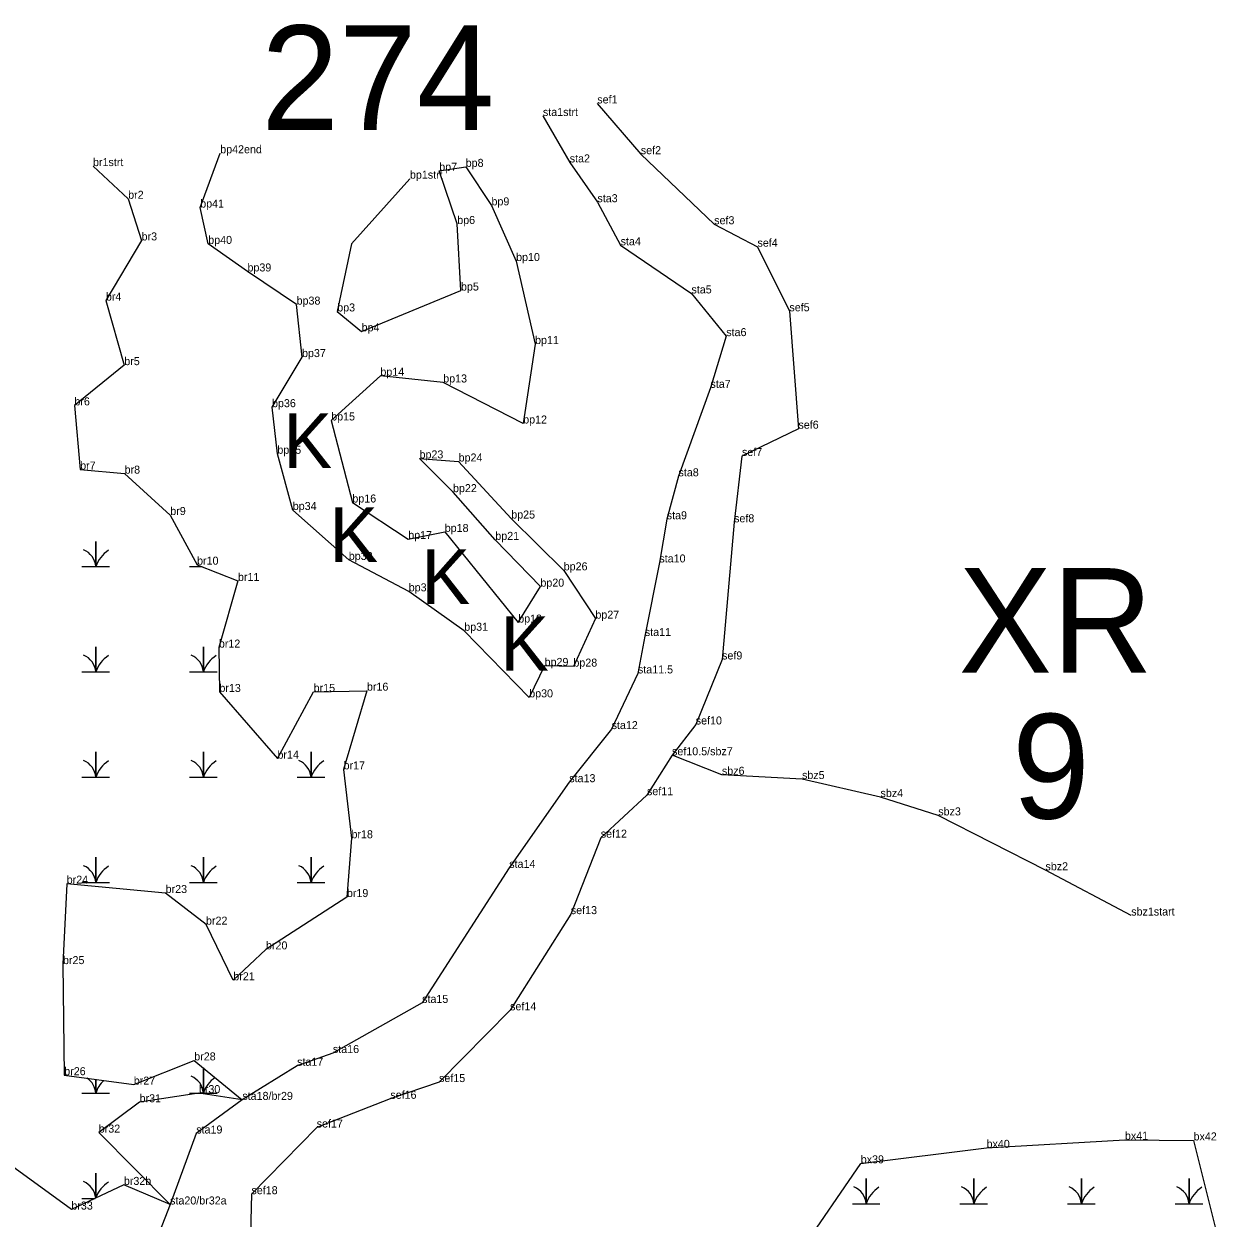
# Model space of a CAD drawing. Extents: x 2072529 to 2268796, y 436423 to 470406.
# Drawn here: x 2233128 to 2233875, y 438303 to 439049 of the extents above; entities that cross this region are included whole.
import ezdxf

# ---------------------------------------------------------------- set-up
doc = ezdxf.new("R2010")
doc.units = 0
for name, color, linetype in [('Default', 7, 'Continuous'), ('Exist Environmental Wetland Boundary Cogo Comment', 7, 'Continuous'), ('Exist Environmental Wetland Boundary Cogo Point CELL', 7, 'Continuous'), ('Exist Hydro Jurisdictional Stream or Body of Water NEU Mitigable Cogo Comment', 7, 'Continuous'), ('Old_Level_20', 7, 'Continuous'), ('Old_Level_52', 7, 'Continuous')]:
    doc.layers.add(name, color=color, linetype=linetype)

msp = doc.modelspace()

# ---------------------------------------------------------------- linework, layer by layer
at = {"layer": 'Exist Environmental Wetland Boundary Cogo Point CELL'}
for points in [[(2233164.16, 438710.03), (2233172.76, 438710.03), (2233172.76, 438725.81), (2233172.76, 438710.03), (2233181.36, 438710.03)], [(2233231.41, 438710.03), (2233239.16, 438710.03)], [(2233164.16, 438644.23), (2233172.76, 438644.23), (2233172.76, 438660.01), (2233172.76, 438644.23), (2233181.36, 438644.23)], [(2233231.41, 438644.23), (2233240.01, 438644.23), (2233240.01, 438660.01), (2233240.01, 438644.23), (2233248.61, 438644.23)], [(2233164.16, 438578.43), (2233172.76, 438578.43), (2233172.76, 438594.21), (2233172.76, 438578.43), (2233181.36, 438578.43)], [(2233231.41, 438578.43), (2233240.01, 438578.43), (2233240.01, 438594.21), (2233240.01, 438578.43), (2233248.61, 438578.43)], [(2233298.66, 438578.43), (2233307.26, 438578.43), (2233307.26, 438594.21), (2233307.26, 438578.43), (2233315.86, 438578.43)], [(2233164.16, 438512.63), (2233172.76, 438512.63), (2233172.76, 438528.41), (2233172.76, 438512.63), (2233181.36, 438512.63)], [(2233231.41, 438512.63), (2233240.01, 438512.63), (2233240.01, 438528.41), (2233240.01, 438512.63), (2233248.61, 438512.63)], [(2233298.66, 438512.63), (2233307.26, 438512.63), (2233307.26, 438528.41), (2233307.26, 438512.63), (2233315.86, 438512.63)], [(2233231.41, 438381.03), (2233240.01, 438381.03), (2233240.01, 438396.78)], [(2233240.01, 438396.78), (2233240.01, 438381.03), (2233248.61, 438381.03)], [(2233164.16, 438381.03), (2233172.76, 438381.03), (2233172.76, 438389.55)], [(2233172.76, 438389.55), (2233172.76, 438381.03), (2233181.36, 438381.03)], [(2233172.76, 438315.4), (2233172.76, 438331.01), (2233172.76, 438315.4)], [(2233645.48, 438311.93), (2233654.08, 438311.93), (2233654.08, 438327.71), (2233654.08, 438311.93), (2233662.68, 438311.93)], [(2233712.73, 438311.93), (2233721.33, 438311.93), (2233721.33, 438327.71), (2233721.33, 438311.93), (2233729.93, 438311.93)], [(2233779.98, 438311.93), (2233788.58, 438311.93), (2233788.58, 438327.71), (2233788.58, 438311.93), (2233797.18, 438311.93)], [(2233847.23, 438311.93), (2233855.83, 438311.93), (2233855.83, 438327.71), (2233855.83, 438311.93), (2233864.43, 438311.93)], [(2233164.16, 438315.23), (2233172.4, 438315.23)]]:
    msp.add_lwpolyline(points, dxfattribs=at)
for centre, radius, start, end in [((2233160.49, 438709.15), 12.3, 4.14034, 67.53497), ((2233191, 438703.97), 19.22, 122.12745, 161.62219), ((2233160.49, 438643.35), 12.3, 4.14034, 67.53497), ((2233191, 438638.17), 19.22, 122.12745, 161.62219), ((2233227.74, 438643.35), 12.3, 4.14034, 67.53497), ((2233258.25, 438638.17), 19.22, 122.12745, 161.62219), ((2233160.49, 438577.55), 12.3, 4.14034, 67.53497), ((2233191, 438572.37), 19.22, 122.12745, 161.62219), ((2233227.74, 438577.55), 12.3, 4.14034, 67.53497), ((2233258.25, 438572.37), 19.22, 122.12745, 161.62219), ((2233294.99, 438577.55), 12.3, 4.14034, 67.53497), ((2233325.5, 438572.37), 19.22, 122.12745, 161.62219), ((2233160.49, 438511.75), 12.3, 4.14034, 67.53497), ((2233191, 438506.57), 19.22, 122.12745, 161.62219), ((2233227.74, 438511.75), 12.3, 4.14034, 67.53497), ((2233258.25, 438506.57), 19.22, 122.12745, 161.62219), ((2233294.99, 438511.75), 12.3, 4.14034, 67.53497), ((2233325.5, 438506.57), 19.22, 122.12745, 161.62219), ((2233227.74, 438380.15), 12.3, 4.14034, 67.53497), ((2233258.25, 438374.97), 19.22, 124.68213, 161.62219), ((2233160.49, 438380.15), 12.3, 4.14034, 55.31148), ((2233191, 438374.97), 19.22, 133.6793, 161.62219), ((2233160.49, 438314.35), 12.3, 4.88803, 67.53497), ((2233191, 438309.17), 19.22, 122.12745, 161.0015), ((2233641.81, 438311.04), 12.3, 4.14034, 67.53497), ((2233672.32, 438305.87), 19.22, 122.12745, 161.62219), ((2233709.06, 438311.04), 12.3, 4.14034, 67.53497), ((2233739.57, 438305.87), 19.22, 122.12745, 161.62219), ((2233776.31, 438311.04), 12.3, 4.14034, 67.53497), ((2233806.82, 438305.87), 19.22, 122.12745, 161.62219), ((2233843.56, 438311.04), 12.3, 4.14034, 67.53497), ((2233874.07, 438305.87), 19.22, 122.12745, 161.62219)]:
    msp.add_arc(centre, radius, start, end, dxfattribs=at)
at = {"layer": 'Old_Level_20'}
for p, q in [((2233486.12, 438999.5), (2233486.12, 438999.5)), ((2233452.15, 438991.66), (2233452.15, 438991.66)), ((2233250.54, 438968.37), (2233250.54, 438968.37)), ((2233513.33, 438967.79), (2233513.33, 438967.79)), ((2233171.06, 438960.35), (2233171.06, 438960.35)), ((2233403.91, 438959.87), (2233403.91, 438959.87)), ((2233468.9, 438962.65), (2233468.9, 438962.65)), ((2233387.35, 438957.42), (2233387.35, 438957.42)), ((2233193.01, 438939.93), (2233193.01, 438939.93)), ((2233420.01, 438935.81), (2233420.01, 438935.81)), ((2233486.21, 438937.78), (2233486.21, 438937.78)), ((2233238.03, 438934.45), (2233238.03, 438934.45)), ((2233398.61, 438924.17), (2233398.61, 438924.17)), ((2233559.17, 438924.01), (2233559.17, 438924.01)), ((2233201.42, 438913.9), (2233201.42, 438913.9)), ((2233243.05, 438911.72), (2233243.05, 438911.72)), ((2233500.71, 438910.85), (2233500.71, 438910.85)), ((2233586.22, 438909.97), (2233586.22, 438909.97)), ((2233435.4, 438901.03), (2233435.4, 438901.03)), ((2233267.57, 438894.51), (2233267.57, 438894.51)), ((2233179.1, 438876.33), (2233179.1, 438876.33)), ((2233400.97, 438882.57), (2233400.97, 438882.57)), ((2233544.96, 438880.77), (2233544.96, 438880.77)), ((2233298.26, 438873.8), (2233298.26, 438873.8)), ((2233323.62, 438869.52), (2233323.62, 438869.52)), ((2233606.16, 438869.63), (2233606.16, 438869.63)), ((2233338.88, 438857.06), (2233338.88, 438857.06)), ((2233566.69, 438854.09), (2233566.69, 438854.09)), ((2233447.25, 438849.14), (2233447.25, 438849.14)), ((2233301.66, 438841), (2233301.66, 438841)), ((2233190.6, 438835.95), (2233190.6, 438835.95)), ((2233350.61, 438829.32), (2233350.61, 438829.32)), ((2233389.86, 438825.12), (2233389.86, 438825.12)), ((2233556.83, 438821.76), (2233556.83, 438821.76)), ((2233159.43, 438810.81), (2233159.43, 438810.81)), ((2233282.91, 438809.69), (2233282.91, 438809.69)), ((2233319.87, 438801.39), (2233319.87, 438801.39)), ((2233439.82, 438799.48), (2233439.82, 438799.48)), ((2233611.8, 438796.23), (2233611.8, 438796.23)), ((2233286.24, 438780.56), (2233286.24, 438780.56)), ((2233576.52, 438779.17), (2233576.52, 438779.17)), ((2233375.06, 438777.67), (2233375.06, 438777.67)), ((2233399.5, 438775.74), (2233399.5, 438775.74)), ((2233163.02, 438770.7), (2233163.02, 438770.7)), ((2233190.8, 438768.17), (2233190.8, 438768.17)), ((2233536.87, 438766.48), (2233536.87, 438766.48)), ((2233395.99, 438756.59), (2233395.99, 438756.59)), ((2233333.11, 438750.11), (2233333.11, 438750.11)), ((2233219.34, 438742.29), (2233219.34, 438742.29)), ((2233295.86, 438745.43), (2233295.86, 438745.43)), ((2233432.37, 438740.1), (2233432.37, 438740.1)), ((2233529.52, 438739.65), (2233529.52, 438739.65)), ((2233571.58, 438737.75), (2233571.58, 438737.75)), ((2233368, 438727.3), (2233368, 438727.3)), ((2233390.81, 438731.69), (2233390.81, 438731.69)), ((2233422.42, 438726.76), (2233422.42, 438726.76)), ((2233330.86, 438714.21), (2233330.86, 438714.21)), ((2233524.92, 438712.66), (2233524.92, 438712.66)), ((2233236.09, 438711.26), (2233236.09, 438711.26)), ((2233465.14, 438707.71), (2233465.14, 438707.71)), ((2233261.63, 438701.08), (2233261.63, 438701.08)), ((2233450.58, 438697.52), (2233450.58, 438697.52)), ((2233368.31, 438694.6), (2233368.31, 438694.6)), ((2233436.71, 438675.09), (2233436.71, 438675.09)), ((2233484.94, 438677.54), (2233484.94, 438677.54)), ((2233403.01, 438669.96), (2233403.01, 438669.96)), ((2233249.69, 438659.45), (2233249.69, 438659.45)), ((2233515.84, 438666.68), (2233515.84, 438666.68)), ((2233564.1, 438652.03), (2233564.1, 438652.03)), ((2233453.22, 438647.98), (2233453.22, 438647.98)), ((2233471.2, 438647.57), (2233471.2, 438647.57)), ((2233511.52, 438643.3), (2233511.52, 438643.3)), ((2233250.03, 438631.71), (2233250.03, 438631.71)), ((2233308.92, 438631.76), (2233308.92, 438631.76)), ((2233342.21, 438632.51), (2233342.21, 438632.51)), ((2233443.58, 438628.34), (2233443.58, 438628.34)), ((2233495.08, 438608.51), (2233495.08, 438608.51)), ((2233547.64, 438611.4), (2233547.64, 438611.4)), ((2233286.3, 438590.05), (2233286.3, 438590.05)), ((2233532.82, 438592.15), (2233532.82, 438592.15)), ((2233327.62, 438583.34), (2233327.62, 438583.34)), ((2233564, 438579.97), (2233564, 438579.97)), ((2233614.03, 438577.31), (2233614.03, 438577.31)), ((2233468.61, 438575.33), (2233468.61, 438575.33)), ((2233517.16, 438567.2), (2233517.16, 438567.2)), ((2233663.08, 438566.07), (2233663.08, 438566.07)), ((2233699.15, 438554.56), (2233699.15, 438554.56)), ((2233332.55, 438540.3), (2233332.55, 438540.3)), ((2233488.29, 438540.65), (2233488.29, 438540.65)), ((2233431.11, 438521.76), (2233431.11, 438521.76)), ((2233766.14, 438520.29), (2233766.14, 438520.29)), ((2233154.63, 438511.91), (2233154.63, 438511.91)), ((2233216.43, 438506.06), (2233216.43, 438506.06)), ((2233329.68, 438503.54), (2233329.68, 438503.54)), ((2233469.6, 438492.88), (2233469.6, 438492.88)), ((2233819.71, 438492), (2233819.71, 438492)), ((2233241.66, 438486.32), (2233241.66, 438486.32)), ((2233279.12, 438470.84), (2233279.12, 438470.84)), ((2233152.31, 438461.64), (2233152.31, 438461.64)), ((2233258.71, 438451.55), (2233258.71, 438451.55)), ((2233376.67, 438437.39), (2233376.67, 438437.39)), ((2233431.64, 438432.8), (2233431.64, 438432.8)), ((2233320.95, 438406.06), (2233320.95, 438406.06)), ((2233234.31, 438401.46), (2233234.31, 438401.46)), ((2233298.57, 438398.12), (2233298.57, 438398.12)), ((2233153.08, 438392.21), (2233153.08, 438392.21)), ((2233196.55, 438386.33), (2233196.55, 438386.33)), ((2233387.24, 438387.93), (2233387.24, 438387.93)), ((2233237.2, 438381.03), (2233237.2, 438381.03)), ((2233264.35, 438376.79), (2233264.35, 438376.79)), ((2233264.35, 438376.79), (2233264.35, 438376.79)), ((2233356.82, 438377.47), (2233356.82, 438377.47)), ((2233200.17, 438375.31), (2233200.17, 438375.31)), ((2233174.65, 438356.35), (2233174.65, 438356.35)), ((2233235.56, 438355.78), (2233235.56, 438355.78)), ((2233310.81, 438359.52), (2233310.81, 438359.52)), ((2233729.33, 438346.82), (2233729.33, 438346.82)), ((2233815.78, 438351.89), (2233815.78, 438351.89)), ((2233858.66, 438351.45), (2233858.66, 438351.45)), ((2233650.73, 438337.13), (2233650.73, 438337.13)), ((2233190.35, 438323.66), (2233190.35, 438323.66)), ((2233270.05, 438317.86), (2233270.05, 438317.86)), ((2233219.22, 438311.43), (2233219.22, 438311.43)), ((2233219.22, 438311.43), (2233219.22, 438311.43)), ((2233157.54, 438308.25), (2233157.54, 438308.25))]:
    msp.add_line(p, q, dxfattribs=at)
for points in [[(2233369.08, 438952.48), (2233332.65, 438911.67), (2233323.62, 438869.52), (2233338.88, 438857.06), (2233400.97, 438882.57), (2233398.61, 438924.17), (2233387.35, 438957.42), (2233403.91, 438959.87), (2233420.01, 438935.81), (2233435.4, 438901.03), (2233447.25, 438849.14), (2233439.82, 438799.48), (2233389.86, 438825.12), (2233350.61, 438829.32), (2233319.87, 438801.39), (2233333.11, 438750.11), (2233368, 438727.3), (2233390.81, 438731.69), (2233436.71, 438675.09), (2233450.58, 438697.52), (2233422.42, 438726.76), (2233395.99, 438756.59), (2233375.06, 438777.67), (2233399.5, 438775.74), (2233432.37, 438740.1), (2233465.14, 438707.71), (2233484.94, 438677.54), (2233471.2, 438647.57), (2233453.22, 438647.98), (2233443.58, 438628.34), (2233403.01, 438669.96), (2233368.31, 438694.6), (2233330.86, 438714.21), (2233295.86, 438745.43), (2233286.24, 438780.56), (2233282.91, 438809.69), (2233301.66, 438841), (2233298.26, 438873.8), (2233267.57, 438894.51), (2233243.05, 438911.72), (2233238.03, 438934.45), (2233250.54, 438968.37)], [(2233171.06, 438960.35), (2233193.01, 438939.93), (2233201.42, 438913.9), (2233179.1, 438876.33), (2233190.6, 438835.95), (2233159.43, 438810.81), (2233163.02, 438770.7), (2233190.8, 438768.17), (2233219.34, 438742.29), (2233236.09, 438711.26), (2233261.63, 438701.08), (2233249.69, 438659.45), (2233250.03, 438631.71), (2233286.3, 438590.05), (2233308.92, 438631.76), (2233342.21, 438632.51), (2233327.62, 438583.34), (2233332.55, 438540.3), (2233329.68, 438503.54), (2233279.12, 438470.84), (2233258.71, 438451.55), (2233241.66, 438486.32), (2233216.43, 438506.06), (2233154.63, 438511.91), (2233152.31, 438461.64), (2233153.08, 438392.21), (2233196.55, 438386.33), (2233234.31, 438401.46), (2233264.35, 438376.79), (2233237.2, 438381.03), (2233200.17, 438375.31), (2233174.65, 438356.35), (2233219.22, 438311.43), (2233190.35, 438323.66), (2233157.54, 438308.25), (2233110.77, 438342.31)], [(2233613.07, 438282.03), (2233650.73, 438337.13), (2233729.33, 438346.82), (2233815.78, 438351.89), (2233858.66, 438351.45), (2233874.62, 438287.27)]]:
    msp.add_lwpolyline(points, dxfattribs=at)
at = {"layer": 'Old_Level_52'}
for points in [[(2233486.12, 438999.5), (2233513.33, 438967.79), (2233559.17, 438924.01), (2233586.22, 438909.97), (2233606.16, 438869.63), (2233611.8, 438796.23), (2233576.52, 438779.17), (2233571.58, 438737.75), (2233564.1, 438652.03), (2233547.64, 438611.4), (2233532.82, 438592.15), (2233517.16, 438567.2), (2233488.29, 438540.65), (2233469.6, 438492.88), (2233431.64, 438432.8), (2233387.24, 438387.93), (2233356.82, 438377.47), (2233310.81, 438359.52), (2233270.05, 438317.86), (2233268.69, 438260.03)], [(2233452.15, 438991.66), (2233468.9, 438962.65), (2233486.21, 438937.78), (2233500.71, 438910.85), (2233544.96, 438880.77), (2233566.69, 438854.09), (2233556.83, 438821.76), (2233536.87, 438766.48), (2233529.52, 438739.65), (2233524.92, 438712.66), (2233515.84, 438666.68), (2233511.52, 438643.3), (2233495.08, 438608.51), (2233468.61, 438575.33), (2233431.11, 438521.76), (2233376.67, 438437.39), (2233320.95, 438406.06), (2233298.57, 438398.12), (2233264.35, 438376.79), (2233235.56, 438355.78), (2233219.22, 438311.43), (2233210.7, 438289.64)], [(2233819.71, 438492), (2233766.14, 438520.29), (2233699.15, 438554.56), (2233663.08, 438566.07), (2233614.03, 438577.31), (2233564, 438579.97), (2233532.82, 438592.15)]]:
    msp.add_lwpolyline(points, dxfattribs=at)

# ---------------------------------------------------------------- texts
at = {"layer": 'Default'}
for s, p in [('274', (2233276.11, 438982.9)), ('XR', (2233711.88, 438643.77)), ('9', (2233745.3, 438552.62))]:
    msp.add_text(s, height=65.34, dxfattribs=at).set_placement(p)
at = {"layer": 'Exist Environmental Wetland Boundary Cogo Comment'}
for s, p in [('bp42end', (2233250.54, 438968.37)), ('br1strt', (2233171.06, 438960.35)), ('bp7', (2233387.35, 438957.42)), ('bp8', (2233403.91, 438959.87)), ('bp1strt', (2233369.08, 438952.48)), ('br2', (2233193.01, 438939.93)), ('bp41', (2233238.03, 438934.45)), ('bp9', (2233420.01, 438935.81)), ('bp6', (2233398.61, 438924.17)), ('br3', (2233201.42, 438913.9)), ('bp40', (2233243.05, 438911.72)), ('bp10', (2233435.4, 438901.03)), ('bp39', (2233267.57, 438894.51)), ('bp5', (2233400.97, 438882.57)), ('br4', (2233179.1, 438876.33)), ('bp38', (2233298.26, 438873.8)), ('bp3', (2233323.62, 438869.52)), ('bp4', (2233338.88, 438857.06)), ('bp11', (2233447.25, 438849.14)), ('bp37', (2233301.66, 438841)), ('br5', (2233190.6, 438835.95)), ('bp14', (2233350.61, 438829.32)), ('bp13', (2233389.86, 438825.12)), ('br6', (2233159.43, 438810.81)), ('bp36', (2233282.91, 438809.69)), ('bp15', (2233319.87, 438801.39)), ('bp12', (2233439.82, 438799.48)), ('bp35', (2233286.24, 438780.56)), ('bp23', (2233375.06, 438777.67)), ('bp24', (2233399.5, 438775.74)), ('br7', (2233163.02, 438770.7)), ('br8', (2233190.8, 438768.17)), ('bp22', (2233395.99, 438756.59)), ('bp34', (2233295.86, 438745.43)), ('bp16', (2233333.11, 438750.11)), ('br9', (2233219.34, 438742.29)), ('bp25', (2233432.37, 438740.1)), ('bp18', (2233390.81, 438731.69)), ('bp17', (2233368, 438727.3)), ('bp21', (2233422.42, 438726.76)), ('bp33', (2233330.86, 438714.21)), ('br10', (2233236.09, 438711.26)), ('bp26', (2233465.14, 438707.71)), ('br11', (2233261.63, 438701.08)), ('bp32', (2233368.31, 438694.6)), ('bp20', (2233450.58, 438697.52)), ('bp27', (2233484.94, 438677.54)), ('bp31', (2233403.01, 438669.96)), ('bp19', (2233436.71, 438675.09)), ('br12', (2233249.69, 438659.45)), ('bp29', (2233453.22, 438647.98)), ('bp28', (2233471.2, 438647.57)), ('br15', (2233308.92, 438631.76)), ('br16', (2233342.21, 438632.51)), ('br13', (2233250.03, 438631.71)), ('bp30', (2233443.58, 438628.34)), ('br14', (2233286.3, 438590.05)), ('br17', (2233327.62, 438583.34)), ('br18', (2233332.55, 438540.3)), ('br24', (2233154.63, 438511.91)), ('br23', (2233216.43, 438506.06)), ('br19', (2233329.68, 438503.54)), ('br22', (2233241.66, 438486.32)), ('br20', (2233279.12, 438470.84)), ('br25', (2233152.31, 438461.64)), ('br21', (2233258.71, 438451.55)), ('br28', (2233234.31, 438401.46)), ('br26', (2233153.08, 438392.21)), ('br27', (2233196.55, 438386.33)), ('br30', (2233237.2, 438381.03)), ('br31', (2233200.17, 438375.31)), ('br32', (2233174.65, 438356.35)), ('bx41', (2233815.78, 438351.89)), ('bx42', (2233858.66, 438351.45)), ('bx40', (2233729.33, 438346.82)), ('bx39', (2233650.73, 438337.13)), ('br32b', (2233190.35, 438323.66)), ('br33', (2233157.54, 438308.25))]:
    msp.add_text(s, height=5, dxfattribs=at).set_placement(p)
at = {"layer": 'Exist Environmental Wetland Boundary Cogo Point CELL'}
for p in [(2233290.06, 438771.75), (2233318.79, 438713.02), (2233376.27, 438686.78), (2233425.63, 438644.92)]:
    msp.add_text('K', height=34, dxfattribs=at).set_placement(p)
at = {"layer": 'Exist Hydro Jurisdictional Stream or Body of Water NEU Mitigable Cogo Comment'}
for s, p in [('sef1', (2233486.12, 438999.5)), ('sta1strt', (2233452.15, 438991.66)), ('sef2', (2233513.33, 438967.79)), ('sta2', (2233468.9, 438962.65)), ('sta3', (2233486.21, 438937.78)), ('sef3', (2233559.17, 438924.01)), ('sta4', (2233500.71, 438910.85)), ('sef4', (2233586.22, 438909.97)), ('sta5', (2233544.96, 438880.77)), ('sef5', (2233606.16, 438869.63)), ('sta6', (2233566.69, 438854.09)), ('sta7', (2233556.83, 438821.76)), ('sef6', (2233611.8, 438796.23)), ('sef7', (2233576.52, 438779.17)), ('sta8', (2233536.87, 438766.48)), ('sta9', (2233529.52, 438739.65)), ('sef8', (2233571.58, 438737.75)), ('sta10', (2233524.92, 438712.66)), ('sta11', (2233515.84, 438666.68)), ('sef9', (2233564.1, 438652.03)), ('sta11.5', (2233511.52, 438643.3)), ('sef10', (2233547.64, 438611.4)), ('sta12', (2233495.08, 438608.51)), ('sef10.5/sbz7', (2233532.82, 438592.15)), ('sbz6', (2233564, 438579.97)), ('sta13', (2233468.61, 438575.33)), ('sbz5', (2233614.03, 438577.31)), ('sef11', (2233517.16, 438567.2)), ('sbz4', (2233663.08, 438566.07)), ('sbz3', (2233699.15, 438554.56)), ('sef12', (2233488.29, 438540.65)), ('sta14', (2233431.11, 438521.76)), ('sbz2', (2233766.14, 438520.29)), ('sef13', (2233469.6, 438492.88)), ('sbz1start', (2233819.71, 438492)), ('sta15', (2233376.67, 438437.39)), ('sef14', (2233431.64, 438432.8)), ('sta16', (2233320.95, 438406.06)), ('sta17', (2233298.57, 438398.12)), ('sef15', (2233387.24, 438387.93)), ('sta18/br29', (2233264.35, 438376.79)), ('sef16', (2233356.82, 438377.47)), ('sta19', (2233235.56, 438355.78)), ('sef17', (2233310.81, 438359.52)), ('sta20/br32a', (2233219.22, 438311.43)), ('sef18', (2233270.05, 438317.86))]:
    msp.add_text(s, height=5, dxfattribs=at).set_placement(p)

doc.saveas('drawing.dxf')
